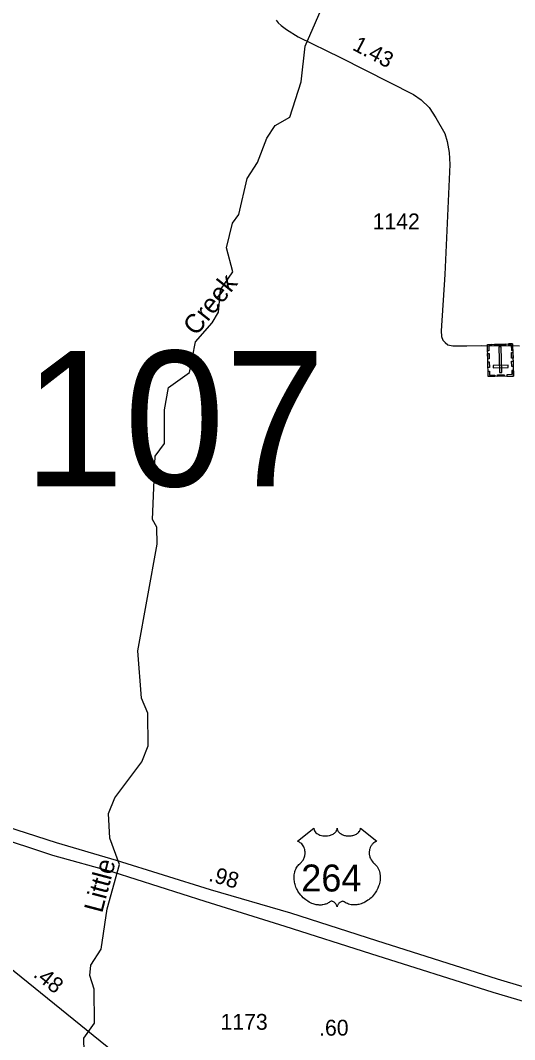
# Model space of a CAD drawing. Extents: x 2220236 to 2384410, y 720751 to 894131.
# Drawn here: x 2225911 to 2229809, y 750400 to 758435 of the extents above; entities that cross this region are included whole.
import ezdxf

# ---------------------------------------------------------------- set-up
doc = ezdxf.new("R2010")
doc.units = 0
doc.layers.add('Default', color=7, linetype='Continuous')

msp = doc.modelspace()

# ---------------------------------------------------------------- linework, layer by layer
at = {"layer": 'Default'}
for points in [[(2226413.4, 750302.6), (2226412.3, 750410.8), (2226494.4, 750530.5), (2226492.5, 750796.3), (2226458.5, 750905.2), (2226466.5, 750987), (2226548.5, 751113.3), (2226595.5, 751430.5), (2226692.5, 751779.5), (2226616.4, 751987.7), (2226606.5, 752181.4), (2226655.5, 752305.1), (2226869.4, 752589.3), (2226918.4, 752716.2), (2226916.6, 752972.2), (2226865.5, 753091.3), (2226837.4, 753465.8), (2226988.6, 754305.7), (2226987.6, 754440.2), (2226953.5, 754499.9), (2226974.6, 754998.1), (2227048.5, 755098.2), (2227046.6, 755364), (2227078.6, 755540.4), (2227244.5, 755658.4), (2227292.5, 755900.1), (2227424.5, 756051.6), (2227473.6, 756135.8), (2227488.5, 756309.4), (2227587.6, 756451.7), (2227536.5, 756643), (2227584.7, 756835.5), (2227634.5, 756903.4), (2227698.5, 757187.4), (2227780.5, 757313.7), (2227854.6, 757505.7), (2227919.6, 757606), (2228035.6, 757672.5), (2228125.6, 757949.4), (2228156.6, 758230.9), (2228319.6, 758608.1)], [(2227927.8, 758435.4), (2227943.4, 758414.6), (2227967.7, 758395.5), (2228011, 758362.6), (2228102.9, 758305.3), (2228435.7, 758142.3), (2229011.1, 757850.9), (2229071.8, 757809.3), (2229135.9, 757748.6), (2229187.9, 757667.1), (2229259, 757544), (2229278, 757479.8), (2229291.9, 757393.1), (2229297.1, 757299.4), (2229257.2, 756432.3), (2229229.5, 755988.3), (2229233, 755941.5), (2229243.4, 755913.7), (2229260.7, 755896.4), (2229283.2, 755877.3), (2229321.4, 755868.6), (2229364.7, 755868.6), (2229430.5, 755868.6), (2229550.1, 755872.1), (2229848.3, 755870.4)], [(2230227, 750711.3), (2229673, 750876.7), (2228722.4, 751178.3), (2228044.2, 751397.2), (2227410, 751581.5), (2226669.3, 751810.5), (2226196.2, 751951.4), (2225719, 752104), (2225266.7, 752256.5)], [(2225264.1, 752147.5), (2225678.4, 752013.1), (2226165.3, 751854), (2226641.4, 751721.1), (2227366.5, 751491), (2227996.2, 751293.3), (2228671, 751078.9), (2229637.3, 750773.9), (2230221.8, 750599.7)], [(2225133.1, 751533.6), (2225266.8, 751415.3), (2225410.2, 751296.9), (2225553.6, 751185.7), (2227107.2, 749930.1)]]:
    msp.add_lwpolyline(points, dxfattribs=at)
for points in [[(2229799.5, 755631.2), (2229600.5, 755626.2), (2229594.1, 755880.8), (2229793.1, 755885.7)], [(2229760.1, 755884.9), (2229760.4, 755873.4), (2229782.4, 755873.9), (2229783.4, 755833.5), (2229794.5, 755833.8), (2229793.2, 755885.7)], [(2229627.2, 755881.6), (2229627.5, 755870.1), (2229605.5, 755869.5), (2229606.5, 755829.1), (2229595.4, 755828.9), (2229594.1, 755880.8)], [(2229607.3, 755808.8), (2229608.4, 755765.5), (2229597, 755765.2), (2229595.9, 755808.5)], [(2229736, 755872.8), (2229651.2, 755870.7), (2229650.9, 755882.1), (2229735.7, 755884.2)], [(2229689.8, 755657.7), (2229708.5, 755658.2), (2229703.4, 755860.9), (2229684.7, 755860.5)], [(2229794.9, 755815.8), (2229796, 755772.5), (2229784.6, 755772.2), (2229783.5, 755815.5)], [(2229608.9, 755742.9), (2229610, 755699.6), (2229598.6, 755699.3), (2229597.5, 755742.6)], [(2229796.6, 755748.6), (2229797.7, 755705.3), (2229786.3, 755705), (2229785.2, 755748.3)], [(2229599.3, 755669.5), (2229610.7, 755669.8), (2229611.5, 755637.7), (2229652, 755638.7), (2229652.3, 755627.5), (2229600.4, 755626.2)], [(2229757, 755698.2), (2229756.5, 755716.9), (2229638.8, 755713.9), (2229639.3, 755695.2)], [(2229798.4, 755674.5), (2229787.1, 755674.2), (2229787.9, 755642), (2229747.3, 755641), (2229747.6, 755629.9), (2229799.5, 755631.2)], [(2229725.5, 755629.3), (2229673.7, 755628.1), (2229673.4, 755639.4), (2229725.2, 755640.7)], [(2228225, 752066.7), (2228225.3, 752061.4), (2228226.6, 752055.1), (2228227.6, 752051.8), (2228230.6, 752045.6), (2228235.4, 752038.2), (2228242.2, 752031), (2228249.9, 752024.7), (2228255.1, 752021.3), (2228263.8, 752016.6), (2228273.8, 752012.4), (2228284.9, 752009.2), (2228296.2, 752007), (2228308.6, 752005.6), (2228320.8, 752005.4), (2228334, 752006.3), (2228348.6, 752009.2), (2228355.4, 752010.9), (2228362.9, 752013.5), (2228369.9, 752016.4), (2228377.5, 752020.5), (2228383.7, 752024.4), (2228388.5, 752027.9), (2228395.3, 752034.5), (2228400.8, 752041.2), (2228403, 752045), (2228405, 752048.7), (2228407.7, 752056.4), (2228408.5, 752059.8), (2228409, 752067), (2228409.5, 752061), (2228410.1, 752057.3), (2228411.1, 752053.6), (2228412.6, 752049.7), (2228415.3, 752044.3), (2228418.3, 752039.7), (2228424.1, 752032.9), (2228427.7, 752029.6), (2228430.9, 752026.9), (2228439.6, 752020.9), (2228449.9, 752015.8), (2228454.9, 752013.6), (2228460, 752011.7), (2228466.6, 752009.8), (2228473.3, 752008.2), (2228480, 752007), (2228486.9, 752006), (2228493.8, 752005.5), (2228499.5, 752005.4), (2228506.5, 752005.4), (2228513, 752005.8), (2228519.6, 752006.6), (2228526.9, 752007.8), (2228532.7, 752009.1), (2228540.5, 752011.1), (2228547.5, 752013.6), (2228553.6, 752016.3), (2228561.6, 752020.5), (2228568, 752024.5), (2228572.8, 752028.3), (2228578.4, 752033.5), (2228583.7, 752039.6), (2228586.8, 752044.1), (2228589, 752048.7), (2228591.1, 752053.6), (2228592.3, 752058.8), (2228592.9, 752063.3), (2228593, 752067.1), (2228721.6, 751964.6), (2228718.6, 751963.5), (2228711.6, 751960.1), (2228706.1, 751956.8), (2228697.2, 751950.6), (2228693.4, 751947.2), (2228689.6, 751943.6), (2228686.1, 751939.8), (2228683.1, 751936.2), (2228679.3, 751931), (2228676, 751925.9), (2228672.7, 751920.2), (2228670.3, 751915.2), (2228666.4, 751904.9), (2228664.5, 751898.4), (2228663.3, 751892.8), (2228661.8, 751881.3), (2228661.4, 751875.9), (2228661.4, 751870.5), (2228661.7, 751864.8), (2228662.2, 751859.3), (2228663.2, 751853.6), (2228664.1, 751848.6), (2228665.7, 751842.4), (2228668, 751835.3), (2228670.8, 751828.4), (2228676.7, 751817.2), (2228684.2, 751805.8), (2228689.6, 751799.4), (2228694.9, 751794), (2228702.9, 751787.3), (2228707.2, 751783.5), (2228712.1, 751778.5), (2228720.2, 751769.2), (2228723.4, 751764.8), (2228726.7, 751759.8), (2228729.8, 751754.8), (2228732.8, 751749.3), (2228735.2, 751744.5), (2228739.8, 751733.5), (2228743.1, 751722.8), (2228744.6, 751717.1), (2228747, 751704.5), (2228747.9, 751698.3), (2228748.9, 751686), (2228748.9, 751671.1), (2228747.8, 751657), (2228745.1, 751640.5), (2228742.9, 751630.6), (2228739.5, 751619.1), (2228736.3, 751609.2), (2228730.4, 751594.5), (2228725.2, 751583.9), (2228718.4, 751571.4), (2228713.8, 751563.9), (2228708.4, 751555.8), (2228701.6, 751546.5), (2228693.7, 751536.7), (2228684.2, 751526.3), (2228676.6, 751518.6), (2228666.5, 751509.6), (2228660.5, 751504.6), (2228651.8, 751498.1), (2228640, 751490.2), (2228628.3, 751483.4), (2228618.3, 751478.3), (2228609.5, 751474.5), (2228598.1, 751470.2), (2228579.1, 751464.9), (2228572.2, 751463.5), (2228564, 751462.3), (2228556.3, 751461.5), (2228548.9, 751461.1), (2228538.9, 751461.1), (2228528.9, 751461.8), (2228519.5, 751463.2), (2228509.7, 751465.2), (2228499.5, 751468.3), (2228490.2, 751471.9), (2228480.7, 751476.6), (2228464.8, 751486.6), (2228460.2, 751489), (2228457.7, 751489.7), (2228451.5, 751490), (2228445.7, 751488.8), (2228439.8, 751486.4), (2228436.2, 751484.5), (2228431.5, 751481.4), (2228427.8, 751478.5), (2228423.4, 751474.4), (2228420.4, 751470.9), (2228418.1, 751468.1), (2228413.6, 751461.1), (2228412, 751457.7), (2228410.3, 751453.4), (2228408.9, 751447), (2228406.8, 751455.1), (2228404.5, 751460.4), (2228401.8, 751464.9), (2228398.9, 751469), (2228394.4, 751474.1), (2228390.4, 751478), (2228385.5, 751482), (2228380.4, 751485.1), (2228376.2, 751487.2), (2228372.4, 751488.6), (2228367.8, 751489.8), (2228364, 751490.1), (2228360.9, 751490), (2228356.6, 751489), (2228350.8, 751484.8), (2228345.3, 751481), (2228339.3, 751477.3), (2228332.1, 751473.5), (2228326.9, 751471.1), (2228320.7, 751468.7), (2228313.4, 751466.2), (2228305.5, 751464.2), (2228297.4, 751462.6), (2228290.2, 751461.4), (2228282.6, 751460.8), (2228275.6, 751460.5), (2228268.4, 751460.6), (2228261.7, 751461.1), (2228253.8, 751461.8), (2228244.1, 751463.3), (2228236.1, 751465.1), (2228227.6, 751467.4), (2228218.8, 751470.1), (2228209.5, 751473.7), (2228197.8, 751478.8), (2228189.7, 751482.9), (2228176.8, 751490.3), (2228161.8, 751500.7), (2228150.4, 751509.9), (2228142.1, 751517.4), (2228129.9, 751529.9), (2228122.7, 751538), (2228111.4, 751552.6), (2228104.2, 751563.2), (2228099.6, 751570.9), (2228092.7, 751583.4), (2228089, 751591.2), (2228084.1, 751602.6), (2228080.3, 751613), (2228077.1, 751622.9), (2228075.4, 751629.2), (2228072.9, 751640.2), (2228071.5, 751648.1), (2228070, 751658.8), (2228069.2, 751670.1), (2228069.1, 751680.5), (2228069.3, 751689.2), (2228070.3, 751699.3), (2228072, 751710), (2228074.1, 751719.2), (2228075.9, 751725.8), (2228078.7, 751733.9), (2228082.3, 751742.7), (2228086.5, 751751.3), (2228090.6, 751758.3), (2228095.7, 751765.9), (2228100.7, 751772.4), (2228107.3, 751779.5), (2228114.1, 751786.1), (2228120.4, 751791.1), (2228127.8, 751798.4), (2228131.7, 751802.8), (2228136.4, 751809), (2228140.1, 751814.7), (2228143, 751819.8), (2228147, 751827.3), (2228149.3, 751832.9), (2228152.3, 751841.6), (2228153.8, 751847.7), (2228155.3, 751855.5), (2228156.3, 751862.9), (2228156.6, 751872.1), (2228156.4, 751879.7), (2228155.4, 751888.6), (2228153.8, 751897.1), (2228151.7, 751904.5), (2228148.6, 751913), (2228145.6, 751919.3), (2228140.7, 751927.7), (2228135.2, 751935.5), (2228129.6, 751941.9), (2228123.9, 751947.6), (2228118.4, 751951.9), (2228113.2, 751955.6), (2228106.7, 751959.5), (2228100.4, 751962.7), (2228096.4, 751964.2)]]:
    msp.add_lwpolyline(points, close=True, dxfattribs=at)

# ---------------------------------------------------------------- texts
for s, height, rotation, p in [('1.43', 125, 332.20943, (2228522.3, 758206.8)), ('Creek', 150, 51.68884, (2227298.7, 755940.6)), ('Little', 150, 75.23681, (2226555.6, 751391.8)), ('.98', 125, 343.79356, (2227389, 751652.7)), ('.48', 125, 321.05466, (2226005.5, 750900.9)), ('.60', 125, 0.37448, (2228267.2, 750430.1))]:
    msp.add_text(s, height=height, rotation=rotation, dxfattribs=at).set_placement(p)
for s, height, p in [('1142', 125, (2228689.1, 756787.5)), ('107', 1066.27, (2225936.8, 754762.4)), ('264', 212.5, (2228126.2, 751567.4)), ('1173', 125, (2227489.5, 750477.2))]:
    msp.add_text(s, height=height, dxfattribs=at).set_placement(p)

doc.saveas('drawing.dxf')
